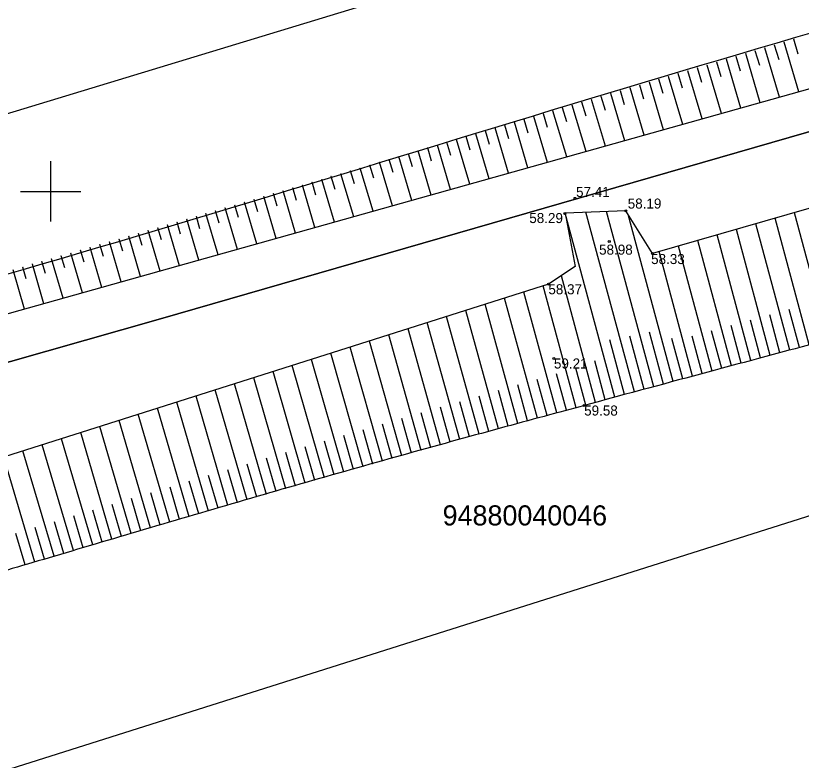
# Model space of a CAD drawing. Extents: x 616607 to 617499, y 408385 to 409695.
# Drawn here: x 616798.26 to 616837.34, y 408521.7 to 408558.74 of the extents above; entities that cross this region are included whole.
import ezdxf

# ---------------------------------------------------------------- set-up
doc = ezdxf.new("R2010")
doc.units = 0
for name, color, linetype in [('GEOD_ELEM_####_####_#', 7, 'Continuous'), ('HIDG_GRAV_####_####_#', 7, 'Continuous'), ('RAMI_UZMR_####_####_#', 7, 'Continuous'), ('RELJ_AATZ_####_TKST_#', 7, 'Continuous'), ('RELJ_ELEM_####_####_#', 7, 'Continuous'), ('RELJ_NOGA_####_####_#', 7, 'Continuous'), ('ROBZ_IERR_####_####_#', 7, 'Continuous'), ('ROBZ_UZMR_####_####_#', 7, 'Continuous'), ('ROBZ_UZMR_####_TKST_#', 7, 'Continuous')]:
    doc.layers.add(name, color=color, linetype=linetype)

# ---------------------------------------------------------------- blocks, each defined once
blk = doc.blocks.new('PKT')
at = {"layer": 'RELJ_ELEM_####_####_#'}
blk.add_circle((0, 0), 0.05, dxfattribs=at)
blk = doc.blocks.new('KRUSTS')
at = {"layer": 'GEOD_ELEM_####_####_#'}
for p, q in [((0, 1.5), (0, 0)), ((-1.5, 0), (0, 0)), ((0, 0), (0, -1.5)), ((0, 0), (1.5, 0))]:
    blk.add_line(p, q, dxfattribs=at)

msp = doc.modelspace()

# ---------------------------------------------------------------- linework, layer by layer
at = {"layer": 'HIDG_GRAV_####_####_#'}
for points in [[(616726.56, 408522.413), (616768.796, 408535.775), (616917.84, 408577.602)], [(616935.727, 408576.737), (616858.974, 408555.268), (616829.937, 408546.914), (616828.609, 408549.04), (616825.59, 408548.927), (616826.098, 408546.263), (616824.758, 408545.383), (616765.45, 408526.57), (616717.618, 408497.675)]]:
    msp.add_lwpolyline(points, dxfattribs=at)
at = {"layer": 'RAMI_UZMR_####_####_#'}
for points in [[(617191.828, 409115.62), (617145.545, 408952.8), (617072.809, 408766.141), (616965.332, 408652.076), (616939.432, 408594.661), (616924.839, 408592.467), (616706.433, 408526.081), (616666.426, 408467.691)], [(616666.426, 408467.691), (616675.529, 408457.882), (616687.228, 408463.356), (616723.888, 408465.775), (616753.554, 408507.232), (616948.282, 408568.831), (616981.528, 408608.531), (617014.563, 408672.892), (617101.571, 408748.246), (617213.472, 409074.039)]]:
    msp.add_lwpolyline(points, dxfattribs=at)
at = {"layer": 'RELJ_NOGA_####_####_#'}
for p, q in [((616836.953, 408557.584), (616837.173, 408556.842)), ((616836.953, 408557.584), (616836.953, 408557.584)), ((616835.515, 408557.158), (616836.242, 408554.703)), ((616835.515, 408557.158), (616835.515, 408557.157)), ((616835.994, 408557.3), (616836.213, 408556.562)), ((616835.994, 408557.3), (616835.994, 408557.3)), ((616836.474, 408557.442), (616837.205, 408554.973)), ((616836.474, 408557.442), (616836.474, 408557.441)), ((616834.077, 408556.732), (616834.293, 408556.002)), ((616834.077, 408556.732), (616834.077, 408556.732)), ((616834.556, 408556.874), (616835.279, 408554.433)), ((616834.556, 408556.874), (616834.556, 408556.873)), ((616835.035, 408557.016), (616835.253, 408556.282)), ((616835.035, 408557.016), (616835.035, 408557.016)), ((616833.118, 408556.447), (616833.333, 408555.722)), ((616833.118, 408556.447), (616833.118, 408556.447)), ((616833.597, 408556.59), (616834.317, 408554.163)), ((616833.597, 408556.59), (616833.598, 408556.589)), ((616831.68, 408556.021), (616832.392, 408553.622)), ((616831.68, 408556.021), (616831.68, 408556.02)), ((616832.159, 408556.163), (616832.373, 408555.441)), ((616832.159, 408556.163), (616832.159, 408556.163)), ((616832.639, 408556.305), (616833.355, 408553.893)), ((616832.639, 408556.305), (616832.639, 408556.304)), ((616830.242, 408555.594), (616830.454, 408554.881)), ((616830.242, 408555.594), (616830.242, 408555.594)), ((616830.721, 408555.736), (616831.429, 408553.352)), ((616830.721, 408555.736), (616830.722, 408555.735)), ((616831.201, 408555.879), (616831.413, 408555.161)), ((616831.201, 408555.879), (616831.201, 408555.878)), ((616828.804, 408555.167), (616829.504, 408552.812)), ((616828.804, 408555.167), (616828.804, 408555.166)), ((616829.283, 408555.309), (616829.494, 408554.6)), ((616829.283, 408555.309), (616829.283, 408555.309)), ((616829.763, 408555.451), (616830.466, 408553.082)), ((616829.763, 408555.451), (616829.763, 408555.451)), ((616827.845, 408554.882), (616828.541, 408552.542)), ((616827.845, 408554.882), (616827.846, 408554.881)), ((616828.325, 408555.024), (616828.534, 408554.32)), ((616828.325, 408555.024), (616828.325, 408555.024)), ((616826.408, 408554.455), (616826.614, 408553.759)), ((616826.408, 408554.455), (616826.408, 408554.455)), ((616826.887, 408554.597), (616827.578, 408552.271)), ((616826.887, 408554.597), (616826.887, 408554.596)), ((616827.366, 408554.74), (616827.574, 408554.04)), ((616827.366, 408554.74), (616827.366, 408554.739)), ((616824.97, 408554.028), (616825.652, 408551.731)), ((616824.97, 408554.028), (616824.97, 408554.027)), ((616825.449, 408554.17), (616825.654, 408553.479)), ((616825.449, 408554.17), (616825.449, 408554.17)), ((616825.928, 408554.312), (616826.615, 408552.001)), ((616825.928, 408554.312), (616825.929, 408554.312)), ((616823.532, 408553.601), (616823.734, 408552.918)), ((616823.532, 408553.601), (616823.532, 408553.6)), ((616824.011, 408553.743), (616824.689, 408551.461)), ((616824.011, 408553.743), (616824.011, 408553.742)), ((616824.49, 408553.885), (616824.694, 408553.199)), ((616824.49, 408553.885), (616824.49, 408553.885)), ((616822.573, 408553.316), (616822.775, 408552.638)), ((616822.573, 408553.316), (616822.573, 408553.316)), ((616823.052, 408553.458), (616823.726, 408551.191)), ((616823.052, 408553.458), (616823.053, 408553.457)), ((616821.135, 408552.889), (616821.8, 408550.65)), ((616821.135, 408552.889), (616821.135, 408552.888)), ((616821.615, 408553.031), (616821.815, 408552.357)), ((616821.615, 408553.031), (616821.615, 408553.031)), ((616822.094, 408553.174), (616822.763, 408550.92)), ((616822.094, 408553.174), (616822.094, 408553.173)), ((616819.697, 408552.462), (616819.895, 408551.797)), ((616819.697, 408552.462), (616819.697, 408552.462)), ((616820.177, 408552.604), (616820.837, 408550.38)), ((616820.177, 408552.604), (616820.177, 408552.603)), ((616820.656, 408552.747), (616820.855, 408552.077)), ((616820.656, 408552.747), (616820.656, 408552.746)), ((616818.259, 408552.036), (616818.91, 408549.839)), ((616818.259, 408552.036), (616818.259, 408552.035)), ((616818.738, 408552.178), (616818.934, 408551.517)), ((616818.738, 408552.178), (616818.739, 408552.177)), ((616819.218, 408552.32), (616819.874, 408550.109)), ((616819.218, 408552.32), (616819.218, 408552.319)), ((616817.3, 408551.751), (616817.947, 408549.569)), ((616817.3, 408551.751), (616817.301, 408551.75)), ((616817.78, 408551.893), (616817.974, 408551.237)), ((616817.78, 408551.893), (616817.78, 408551.893)), ((616815.862, 408551.325), (616816.054, 408550.677)), ((616815.862, 408551.325), (616815.862, 408551.325)), ((616816.342, 408551.467), (616816.984, 408549.298)), ((616816.342, 408551.467), (616816.342, 408551.466)), ((616816.821, 408551.609), (616817.014, 408550.956)), ((616816.821, 408551.609), (616816.821, 408551.609)), ((616814.424, 408550.899), (616815.058, 408548.758)), ((616814.424, 408550.899), (616814.424, 408550.898)), ((616814.903, 408551.041), (616815.094, 408550.397)), ((616814.903, 408551.041), (616814.903, 408551.041)), ((616815.383, 408551.183), (616816.021, 408549.028)), ((616815.383, 408551.183), (616815.383, 408551.182)), ((616812.985, 408550.474), (616813.174, 408549.837)), ((616812.985, 408550.474), (616812.986, 408550.474)), ((616813.465, 408550.616), (616814.094, 408548.487)), ((616813.465, 408550.616), (616813.465, 408550.615)), ((616813.944, 408550.757), (616814.134, 408550.117)), ((616813.944, 408550.757), (616813.945, 408550.757)), ((616812.026, 408550.19), (616812.213, 408549.558)), ((616812.026, 408550.19), (616812.027, 408550.19)), ((616812.506, 408550.332), (616813.131, 408548.217)), ((616812.506, 408550.332), (616812.506, 408550.331)), ((616810.588, 408549.766), (616811.204, 408547.676)), ((616810.588, 408549.766), (616810.588, 408549.765)), ((616811.067, 408549.907), (616811.253, 408549.279)), ((616811.067, 408549.907), (616811.067, 408549.907)), ((616811.547, 408550.049), (616812.168, 408547.947)), ((616811.547, 408550.049), (616811.547, 408550.048)), ((616809.149, 408549.342), (616809.332, 408548.72)), ((616809.149, 408549.342), (616809.149, 408549.341)), ((616809.629, 408549.483), (616810.241, 408547.406)), ((616809.629, 408549.483), (616809.629, 408549.482)), ((616810.108, 408549.624), (616810.292, 408548.999)), ((616810.108, 408549.624), (616810.108, 408549.624)), ((616807.71, 408548.918), (616808.314, 408546.865)), ((616807.71, 408548.918), (616807.71, 408548.917)), ((616808.19, 408549.059), (616808.372, 408548.442)), ((616808.19, 408549.059), (616808.19, 408549.059)), ((616808.669, 408549.2), (616809.277, 408547.136)), ((616808.669, 408549.2), (616808.67, 408549.2)), ((616828.069, 408539.766), (616825.597, 408548.927)), ((616829.035, 408540.026), (616826.622, 408548.966)), ((616830, 408540.287), (616827.651, 408549.004)), ((616838.691, 408542.624), (616836.994, 408548.944)), ((616806.751, 408548.636), (616807.35, 408546.595)), ((616806.751, 408548.636), (616806.751, 408548.635)), ((616807.23, 408548.777), (616807.411, 408548.163)), ((616807.23, 408548.777), (616807.23, 408548.777)), ((616830.966, 408540.547), (616828.729, 408548.849)), ((616837.726, 408542.365), (616836.033, 408548.668)), ((616805.311, 408548.214), (616805.489, 408547.606)), ((616805.311, 408548.214), (616805.311, 408548.213)), ((616805.791, 408548.354), (616806.386, 408546.324)), ((616805.791, 408548.354), (616805.791, 408548.353)), ((616806.271, 408548.495), (616806.45, 408547.885)), ((616806.271, 408548.495), (616806.271, 408548.495)), ((616835.794, 408541.846), (616834.109, 408548.114)), ((616836.76, 408542.106), (616835.071, 408548.391)), ((616803.872, 408547.792), (616804.459, 408545.784)), ((616803.872, 408547.792), (616803.872, 408547.791)), ((616804.352, 408547.932), (616804.529, 408547.328)), ((616804.352, 408547.932), (616804.352, 408547.932)), ((616804.832, 408548.073), (616805.424, 408546.054)), ((616804.832, 408548.073), (616804.832, 408548.072)), ((616834.828, 408541.586), (616833.148, 408547.838)), ((616802.432, 408547.371), (616802.607, 408546.773)), ((616802.432, 408547.371), (616802.432, 408547.37)), ((616802.912, 408547.511), (616803.497, 408545.513)), ((616802.912, 408547.511), (616802.912, 408547.51)), ((616803.392, 408547.651), (616803.568, 408547.051)), ((616803.392, 408547.651), (616803.392, 408547.651)), ((616833.863, 408541.327), (616832.187, 408547.561)), ((616800.992, 408546.95), (616801.57, 408544.973)), ((616800.992, 408546.95), (616800.993, 408546.949)), ((616801.472, 408547.09), (616801.646, 408546.496)), ((616801.472, 408547.09), (616801.472, 408547.09)), ((616801.952, 408547.231), (616802.532, 408545.243)), ((616801.952, 408547.231), (616801.953, 408547.23)), ((616831.931, 408540.807), (616830.261, 408547.007)), ((616832.897, 408541.067), (616831.224, 408547.284)), ((616800.032, 408546.671), (616800.605, 408544.702)), ((616800.032, 408546.671), (616800.033, 408546.67)), ((616800.512, 408546.81), (616800.685, 408546.218)), ((616800.512, 408546.81), (616800.512, 408546.81)), ((616798.592, 408546.252), (616798.762, 408545.665)), ((616798.592, 408546.252), (616798.592, 408546.251)), ((616799.072, 408546.391), (616799.642, 408544.432)), ((616799.072, 408546.391), (616799.072, 408546.39)), ((616799.552, 408546.531), (616799.724, 408545.942)), ((616799.552, 408546.531), (616799.552, 408546.531)), ((616798.112, 408546.112), (616798.678, 408544.161)), ((616827.104, 408539.505), (616825.402, 408545.806)), ((616825.174, 408538.982), (616823.537, 408544.996)), ((616826.139, 408539.244), (616824.497, 408545.301)), ((616824.209, 408538.719), (616822.576, 408544.691)), ((616823.244, 408538.454), (616821.616, 408544.387)), ((616822.28, 408538.189), (616820.657, 408544.082)), ((616836.277, 408541.976), (616835.771, 408543.859)), ((616837.243, 408542.235), (616836.736, 408544.124)), ((616820.353, 408537.655), (616818.734, 408543.473)), ((616821.316, 408537.923), (616819.693, 408543.777)), ((616835.311, 408541.716), (616834.806, 408543.594)), ((616819.389, 408537.387), (616817.776, 408543.169)), ((616833.38, 408541.197), (616832.877, 408543.065)), ((616834.346, 408541.457), (616833.842, 408543.329)), ((616818.426, 408537.118), (616816.818, 408542.865)), ((616829.518, 408540.156), (616828.804, 408542.805)), ((616830.483, 408540.417), (616829.787, 408542.999)), ((616831.449, 408540.677), (616830.906, 408542.691)), ((616832.414, 408540.937), (616831.913, 408542.8)), ((616816.501, 408536.576), (616814.899, 408542.256)), ((616817.464, 408536.848), (616815.856, 408542.56)), ((616828.552, 408539.896), (616827.819, 408542.611)), ((616815.539, 408536.304), (616813.94, 408541.952)), ((616836.277, 408541.976), (616836.277, 408541.976)), ((616836.76, 408542.106), (616836.76, 408542.106)), ((616837.243, 408542.235), (616837.243, 408542.236)), ((616814.577, 408536.031), (616812.981, 408541.647)), ((616827.587, 408539.635), (616827.063, 408541.573)), ((616834.828, 408541.586), (616834.828, 408541.587)), ((616835.311, 408541.716), (616835.311, 408541.716)), ((616835.794, 408541.846), (616835.794, 408541.847)), ((616813.615, 408535.758), (616812.021, 408541.343)), ((616826.621, 408539.374), (616826.123, 408541.217)), ((616833.38, 408541.197), (616833.38, 408541.197)), ((616833.863, 408541.327), (616833.862, 408541.328)), ((616834.346, 408541.457), (616834.346, 408541.457)), ((616811.692, 408535.208), (616810.105, 408540.735)), ((616812.653, 408535.483), (616811.063, 408541.039)), ((616825.656, 408539.113), (616825.165, 408540.924)), ((616831.931, 408540.807), (616831.931, 408540.808)), ((616832.414, 408540.937), (616832.414, 408540.937)), ((616832.897, 408541.067), (616832.897, 408541.068)), ((616810.731, 408534.931), (616809.147, 408540.431)), ((616823.727, 408538.587), (616823.237, 408540.372)), ((616824.691, 408538.85), (616824.202, 408540.649)), ((616830.483, 408540.417), (616830.483, 408540.417)), ((616830.966, 408540.547), (616830.966, 408540.548)), ((616831.449, 408540.677), (616831.449, 408540.677)), ((616809.77, 408534.655), (616808.19, 408540.128)), ((616822.762, 408538.322), (616822.274, 408540.095)), ((616829.035, 408540.026), (616829.035, 408540.027)), ((616829.518, 408540.156), (616829.517, 408540.157)), ((616830, 408540.287), (616830, 408540.288)), ((616807.849, 408534.099), (616806.276, 408539.521)), ((616808.809, 408534.377), (616807.233, 408539.824)), ((616820.834, 408537.789), (616820.349, 408539.54)), ((616821.798, 408538.056), (616821.311, 408539.818)), ((616827.587, 408539.635), (616827.587, 408539.636)), ((616828.069, 408539.766), (616828.069, 408539.767)), ((616828.552, 408539.896), (616828.552, 408539.896)), ((616806.889, 408533.82), (616805.319, 408539.217)), ((616819.871, 408537.521), (616819.387, 408539.261)), ((616826.139, 408539.244), (616826.138, 408539.245)), ((616826.621, 408539.374), (616826.621, 408539.375)), ((616827.104, 408539.505), (616827.104, 408539.506)), ((616805.928, 408533.54), (616804.36, 408538.913)), ((616818.908, 408537.253), (616818.424, 408538.982)), ((616824.691, 408538.85), (616824.691, 408538.851)), ((616825.174, 408538.982), (616825.173, 408538.983)), ((616825.656, 408539.113), (616825.656, 408539.113)), ((616804.969, 408533.26), (616803.403, 408538.609)), ((616816.982, 408536.712), (616816.5, 408538.421)), ((616817.945, 408536.983), (616817.463, 408538.702)), ((616823.244, 408538.454), (616823.244, 408538.455)), ((616823.727, 408538.587), (616823.726, 408538.587)), ((616824.209, 408538.719), (616824.209, 408538.72)), ((616803.049, 408532.697), (616801.493, 408538.003)), ((616804.009, 408532.979), (616802.45, 408538.307)), ((616816.02, 408536.44), (616815.539, 408538.139)), ((616821.798, 408538.056), (616821.798, 408538.056)), ((616822.28, 408538.189), (616822.28, 408538.19)), ((616822.762, 408538.322), (616822.762, 408538.322)), ((616802.09, 408532.415), (616800.535, 408537.7)), ((616814.096, 408535.895), (616813.618, 408537.575)), ((616815.058, 408536.168), (616814.578, 408537.857)), ((616820.353, 408537.655), (616820.352, 408537.656)), ((616820.834, 408537.789), (616820.834, 408537.789)), ((616821.316, 408537.923), (616821.316, 408537.924)), ((616801.131, 408532.133), (616799.578, 408537.396)), ((616813.134, 408535.62), (616812.657, 408537.292)), ((616818.908, 408537.253), (616818.908, 408537.253)), ((616819.389, 408537.387), (616819.389, 408537.388)), ((616819.871, 408537.521), (616819.871, 408537.522)), ((616799.212, 408531.566), (616797.665, 408536.789)), ((616800.171, 408531.85), (616798.622, 408537.093)), ((616812.173, 408535.345), (616811.697, 408537.008)), ((616817.464, 408536.848), (616817.463, 408536.848)), ((616817.945, 408536.983), (616817.945, 408536.983)), ((616818.426, 408537.118), (616818.426, 408537.119)), ((616810.25, 408534.793), (616809.776, 408536.439)), ((616811.211, 408535.07), (616810.736, 408536.724)), ((616816.02, 408536.44), (616816.02, 408536.441)), ((616816.501, 408536.576), (616816.501, 408536.577)), ((616816.982, 408536.712), (616816.982, 408536.712)), ((616809.29, 408534.516), (616808.817, 408536.154)), ((616814.577, 408536.031), (616814.576, 408536.032)), ((616815.058, 408536.168), (616815.058, 408536.168)), ((616815.539, 408536.304), (616815.539, 408536.305)), ((616808.329, 408534.238), (616807.856, 408535.868)), ((616813.134, 408535.62), (616813.134, 408535.621)), ((616813.615, 408535.758), (616813.615, 408535.759)), ((616814.096, 408535.895), (616814.096, 408535.895)), ((616806.408, 408533.68), (616805.939, 408535.296)), ((616807.369, 408533.959), (616806.897, 408535.582)), ((616812.173, 408535.345), (616812.173, 408535.346)), ((616812.653, 408535.483), (616812.653, 408535.484)), ((616805.448, 408533.4), (616804.979, 408535.008)), ((616810.731, 408534.931), (616810.731, 408534.932)), ((616811.211, 408535.07), (616811.211, 408535.07)), ((616811.692, 408535.208), (616811.692, 408535.209)), ((616804.489, 408533.119), (616804.02, 408534.721)), ((616809.29, 408534.516), (616809.29, 408534.516)), ((616809.77, 408534.655), (616809.77, 408534.656)), ((616810.25, 408534.793), (616810.25, 408534.793)), ((616802.569, 408532.556), (616802.102, 408534.145)), ((616803.529, 408532.838), (616803.061, 408534.433)), ((616807.849, 408534.099), (616807.849, 408534.1)), ((616808.329, 408534.238), (616808.329, 408534.238)), ((616808.809, 408534.377), (616808.809, 408534.378)), ((616801.61, 408532.274), (616801.145, 408533.856)), ((616806.408, 408533.68), (616806.408, 408533.68)), ((616806.889, 408533.82), (616806.888, 408533.82)), ((616807.369, 408533.959), (616807.369, 408533.959)), ((616799.692, 408531.708), (616799.228, 408533.278)), ((616800.651, 408531.991), (616800.186, 408533.567)), ((616805.448, 408533.4), (616805.448, 408533.4)), ((616805.928, 408533.54), (616805.928, 408533.541)), ((616798.733, 408531.424), (616798.27, 408532.988)), ((616804.009, 408532.979), (616804.008, 408532.98)), ((616804.489, 408533.119), (616804.489, 408533.12)), ((616804.969, 408533.26), (616804.968, 408533.261)), ((616802.569, 408532.556), (616802.569, 408532.557)), ((616803.049, 408532.697), (616803.049, 408532.698)), ((616803.529, 408532.838), (616803.529, 408532.838)), ((616801.131, 408532.133), (616801.13, 408532.134)), ((616801.61, 408532.274), (616801.61, 408532.274)), ((616802.09, 408532.415), (616802.09, 408532.416)), ((616799.692, 408531.708), (616799.692, 408531.708)), ((616800.171, 408531.85), (616800.171, 408531.851)), ((616800.651, 408531.991), (616800.651, 408531.992)), ((616798.733, 408531.424), (616798.733, 408531.425)), ((616799.212, 408531.566), (616799.212, 408531.567))]:
    msp.add_line(p, q, dxfattribs=at)
msp.add_open_spline([(616975.731, 408606.41), (616971.71, 408604.144), (616967.689, 408601.878), (616963.668, 408599.612), (616962.341, 408598.864), (616961.192, 408597.791), (616960.311, 408596.511), (616959.39, 408595.173), (616958.675, 408593.776), (616958.002, 408592.329), (616957.302, 408590.825), (616956.736, 408589.272), (616956.015, 408587.778), (616955.313, 408586.324), (616954.582, 408584.882), (616953.626, 408583.572), (616952.496, 408582.025), (616951.261, 408580.593), (616950.022, 408579.143), (616948.785, 408577.695), (616947.537, 408576.278), (616946.22, 408574.895), (616945.626, 408574.271), (616944.957, 408573.742), (616944.225, 408573.278), (616943.451, 408572.788), (616942.648, 408572.387), (616941.804, 408572.051), (616941, 408571.73), (616940.2, 408571.414), (616939.368, 408571.187), (616938.69, 408571.002), (616938.005, 408570.852), (616937.329, 408570.663), (616918.615, 408565.441), (616899.903, 408560.204), (616881.253, 408554.75), (616874.57, 408552.796), (616867.991, 408550.484), (616861.269, 408548.669), (616855.483, 408547.106), (616849.688, 408545.577), (616843.9, 408544.023), (616838.111, 408542.469), (616832.323, 408540.916), (616826.537, 408539.352), (616816.497, 408536.637), (616806.51, 408533.737), (616796.541, 408530.774), (616791.553, 408529.292), (616786.584, 408527.751), (616781.609, 408526.226), (616776.622, 408524.697), (616771.656, 408523.11), (616766.688, 408521.515), (616762.607, 408520.204), (616758.677, 408518.521), (616754.775, 408516.687), (616750.921, 408514.875), (616747.341, 408512.653), (616743.915, 408510.109), (616740.341, 408507.454), (616736.942, 408504.677), (616733.801, 408501.555), (616732.131, 408499.895), (616730.49, 408498.223), (616728.926, 408496.468), (616728.114, 408495.556), (616727.318, 408494.632), (616726.518, 408493.709), (616725.695, 408492.76), (616724.91, 408491.864), (616724.122, 408490.803), (616723.665, 408490.187), (616723.18, 408489.459), (616723.332, 408488.764), (616723.537, 408487.829), (616723.949, 408486.896), (616724.213, 408485.954), (616724.975, 408483.236), (616725.742, 408480.486), (616726.381, 408477.738), (616726.631, 408476.667), (616726.554, 408475.507), (616726.221, 408474.429), (616726.043, 408473.855), (616725.77, 408473.346), (616725.415, 408472.86), (616725.226, 408472.602), (616725.032, 408472.37), (616724.813, 408472.14), (616724.582, 408471.898), (616724.347, 408471.683), (616724.071, 408471.48), (616723.783, 408471.268), (616723.475, 408471.091), (616723.13, 408471.039), (616722.812, 408470.991), (616722.494, 408470.986), (616722.176, 408470.982), (616721.543, 408470.975), (616720.901, 408471.154), (616720.278, 408471.02), (616716.569, 408470.219), (616712.93, 408469.339), (616709.261, 408468.478), (616707.424, 408468.047), (616705.589, 408467.613), (616703.751, 408467.182), (616701.927, 408466.754), (616700.076, 408466.424), (616698.236, 408466.115), (616695.42, 408465.64), (616692.315, 408465.565), (616689.691, 408467.073), (616684.319, 408470.158), (616679.892, 408473.486), (616675.008, 408476.777), (616674.831, 408476.896), (616674.652, 408477.012), (616674.483, 408477.14), (616674.175, 408477.376), (616674.46, 408477.978), (616674.696, 408478.288), (616675.427, 408479.251), (616676.165, 408480.2), (616676.939, 408481.135), (616677.893, 408482.289), (616678.812, 408483.429), (616679.848, 408484.532), (616681.078, 408485.839), (616682.698, 408486.726), (616684.412, 408487.237), (616686.183, 408487.764), (616687.958, 408488.143), (616689.768, 408488.401), (616691.642, 408488.668), (616693.528, 408488.826), (616695.398, 408489.116), (616696.323, 408489.26), (616697.239, 408489.444), (616698.155, 408489.647), (616699.054, 408489.848), (616699.912, 408490.166), (616700.785, 408490.476), (616703.122, 408491.305), (616705.613, 408491.942), (616707.248, 408494.043), (616707.429, 408494.275), (616707.474, 408494.537), (616707.552, 408494.798), (616707.628, 408495.051), (616707.711, 408495.3), (616707.761, 408495.559), (616707.86, 408496.068), (616707.943, 408496.577), (616707.977, 408497.092), (616708.044, 408498.12), (616708.108, 408499.147), (616708.168, 408500.175), (616708.254, 408501.63), (616708.34, 408503.085), (616708.414, 408504.54), (616708.488, 408505.998), (616708.403, 408507.461), (616708.436, 408508.92), (616708.468, 408510.38), (616708.539, 408511.837), (616708.686, 408513.293), (616708.76, 408514.026), (616708.887, 408514.749), (616709.039, 408515.47), (616709.116, 408515.834), (616709.208, 408516.193), (616709.297, 408516.554), (616709.387, 408516.92), (616709.487, 408517.278), (616709.619, 408517.635), (616710.681, 408520.51), (616712.959, 408522.898), (616715.736, 408524.335), (616718.688, 408525.863), (616721.668, 408526.887), (616724.792, 408527.643), (616730.078, 408528.922), (616735.359, 408530.207), (616740.655, 408531.436), (616749.901, 408533.581), (616759.244, 408535.317), (616768.413, 408537.779), (616798.7, 408545.91), (616828.618, 408555.288), (616858.746, 408563.964), (616877.646, 408569.406), (616896.581, 408574.731), (616915.501, 408580.089), (616916.131, 408580.267), (616916.803, 408580.127), (616917.44, 408580.402), (616917.832, 408580.571), (616918.181, 408580.992), (616918.136, 408581.394), (616918.071, 408581.969), (616918.005, 408582.544), (616917.94, 408583.119), (616917.87, 408583.733), (616917.799, 408584.347), (616917.73, 408584.96), (616917.674, 408585.454), (616917.97, 408585.948), (616918.384, 408586.3), (616918.906, 408586.742), (616919.445, 408586.959), (616920.02, 408587.218), (616920.568, 408587.465), (616921.093, 408587.698), (616921.676, 408587.899), (616922.792, 408588.284), (616923.918, 408588.529), (616925.044, 408588.565), (616925.938, 408588.594), (616926.854, 408588.454), (616927.734, 408588.123), (616928.677, 408587.768), (616929.526, 408587.359), (616930.432, 408586.999), (616931.324, 408586.645), (616932.223, 408586.313), (616933.127, 408585.998), (616933.97, 408585.704), (616934.935, 408585.706), (616935.807, 408585.922), (616937.564, 408586.355), (616939.443, 408587.201), (616940.422, 408588.724), (616944.438, 408594.972), (616948.27, 408601.228), (616952.11, 408607.531)], degree=3, dxfattribs=at)
at = {"layer": 'ROBZ_IERR_####_####_#'}
msp.add_lwpolyline([(617055.284, 408797.783), (617087.528, 408757.04), (616999.181, 408676.019), (616968.565, 408608.405), (616958.517, 408604.593), (616940.576, 408582.801), (616889.795, 408568.012), (616805.459, 408543.657), (616730.494, 408522.344), (616717.135, 408556.579)], dxfattribs=at)
at = {"layer": 'ROBZ_UZMR_####_####_#'}
msp.add_lwpolyline([(616704.998, 408460.626), (616695.309, 408466.84), (616688.046, 408471.498), (616708.653, 408488.203), (616730.494, 408522.344), (616805.459, 408543.657), (616889.795, 408568.012), (616940.576, 408582.801), (616958.517, 408604.593), (616968.565, 408608.405), (616974.837, 408605.827), (616993.227, 408598.268)], dxfattribs=at)

# ---------------------------------------------------------------- block references
at = {"layer": 'GEOD_ELEM_####_####_#'}
msp.add_blockref('KRUSTS', (616800, 408550), dxfattribs=at)
at = {"layer": 'RELJ_ELEM_####_####_#'}
for p in [(616826.083, 408549.657), (616825.573, 408548.908), (616828.609, 408549.04), (616827.788, 408547.506), (616829.937, 408546.914), (616824.758, 408545.383), (616825.034, 408541.691), (616826.537, 408539.352)]:
    msp.add_blockref('PKT', p, dxfattribs=at)

# ---------------------------------------------------------------- texts
at = {"layer": 'RELJ_AATZ_####_TKST_#'}
for s, p in [('57.41', (616826.134, 408549.727)), ('58.19', (616828.705, 408549.148)), ('58.29', (616823.808, 408548.427)), ('58.98', (616827.28, 408546.855)), ('58.33', (616829.868, 408546.388)), ('58.37', (616824.758, 408544.883)), ('59.21', (616825.034, 408541.191)), ('59.58', (616826.537, 408538.852))]:
    msp.add_text(s, height=0.5, dxfattribs=at).set_placement(p)
at = {"layer": 'ROBZ_UZMR_####_TKST_#'}
msp.add_text('94880040046', height=1, dxfattribs=at).set_placement((616819.497, 408533.385))

doc.saveas('drawing.dxf')
